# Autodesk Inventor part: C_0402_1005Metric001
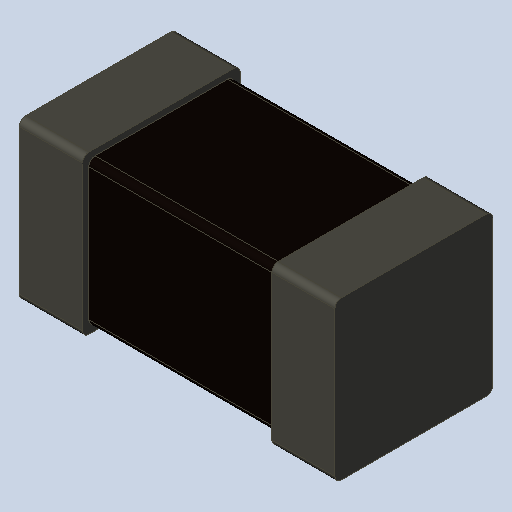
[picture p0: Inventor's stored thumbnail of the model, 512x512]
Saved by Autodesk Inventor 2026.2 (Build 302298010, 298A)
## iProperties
Created: 2026-10
Part Number: C_0402_1005Metric001
Material: Générique
Document SubType Name: Modeling
Designer: mel
Density: 1 g/cm^3
Appearance: Par défaut
Author: mel
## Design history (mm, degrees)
feature "Base1"
node "Solide1"
